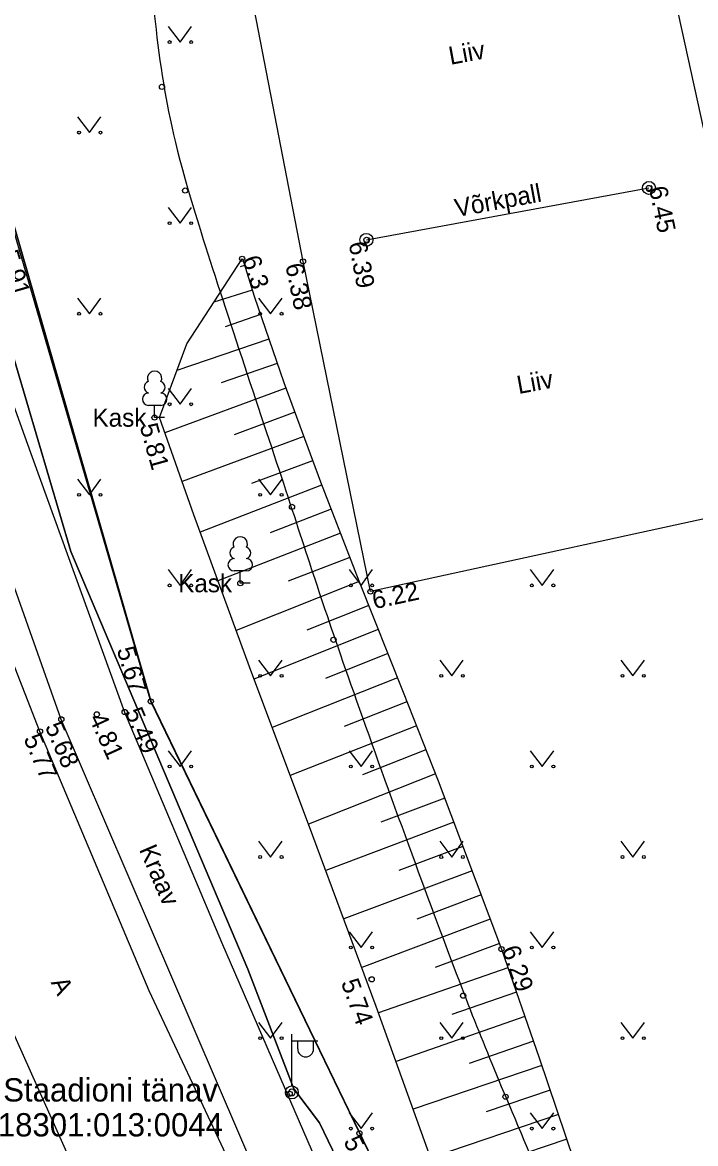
# Model space of a CAD drawing. Extents: x 473307 to 473719, y 6532843 to 6533381.
# Drawn here: x 473404.68 to 473430.7, y 6533111.89 to 6533155.23 of the extents above; entities that cross this region are included whole.
import ezdxf

# ---------------------------------------------------------------- set-up
doc = ezdxf.new("R2010")
doc.units = 0
for name, color, linetype in [('AED', 7, 'Continuous'), ('Default', 7, 'Continuous'), ('HALJASTUS', 7, 'Continuous'), ('KORGUS', 7, 'Continuous'), ('MPKAABEL', 7, 'Continuous'), ('PIIR', 7, 'Continuous'), ('POST', 7, 'Continuous'), ('PUU', 7, 'Continuous'), ('RAJATIS', 7, 'Continuous'), ('RELJEEF', 7, 'Continuous'), ('TEE', 7, 'Continuous'), ('VEEKOGU', 7, 'Continuous'), ('VTRASS', 7, 'Continuous')]:
    doc.layers.add(name, color=color, linetype=linetype)

# ---------------------------------------------------------------- blocks, each defined once
blk = doc.blocks.new('LEHTP1')
at = {"layer": 'Default'}
for p, q in [((0.48, 0.95), (-0.48, 0.95)), ((0, 0), (0, 0.95)), ((0.76, 0), (0, 0))]:
    blk.add_line(p, q, dxfattribs=at)
for centre, radius, start, end in [((0, 3.04), 0.554, 332.5799, 207.4201), ((-0.34, 2.345), 0.465, 109.02174, 253.14154), ((0.34, 2.345), 0.465, 286.85082, 70.98591), ((-0.475, 1.425), 0.475, 90.0016, 269.3953), ((0.475, 1.425), 0.475, 270.6047, 89.9984)]:
    blk.add_arc(centre, radius, start, end, dxfattribs=at)
blk = doc.blocks.new('MEPOST')
at = {"layer": 'Default'}
blk.add_circle((0, 0), 0.5, dxfattribs=at)
for start, end in [(0, 180), (180, 0)]:
    blk.add_arc((0, 0), 0.25, start, end, dxfattribs=at)
blk = doc.blocks.new('VAPOST')
at = {"layer": 'Default'}
for p, q in [((0, 0.5), (0, 4.5)), ((0, 4), (2, 4)), ((0.453, 3.358), (0.453, 4)), ((1.679, 3.358), (1.679, 4))]:
    blk.add_line(p, q, dxfattribs=at)
blk.add_arc((1.066, 3.358), 0.613, 180, 0, dxfattribs=at)
blk = doc.blocks.new('MURU')
at = {"layer": 'Default'}
for p, q in [((-0.927, 1.213), (0, 0)), ((0, 0), (0.891, 1.213))]:
    blk.add_line(p, q, dxfattribs=at)
for centre in [(-0.802, 0), (0.856, 0)]:
    blk.add_circle(centre, 0.11, dxfattribs=at)
blk = doc.blocks.new('PLPOST')
at = {"layer": 'Default'}
blk.add_circle((0, 0), 0.5, dxfattribs=at)
blk.add_arc((0, 0), 0.25, 225, 45, dxfattribs=at)

msp = doc.modelspace()

# ---------------------------------------------------------------- linework, layer by layer
at = {"layer": 'AED'}
msp.add_lwpolyline([(473572.372, 6533059.989), (473562.796, 6533044.25), (473549.715, 6533022.819), (473547.153, 6533018.61), (473538.777, 6533017.059), (473515.614, 6533013.019), (473502.84, 6533010.765), (473486.499, 6533007.9), (473486.322, 6533008.043), (473484.734, 6533009.635), (473455.331, 6533045.745), (473429.609, 6533087.699), (473409.64, 6533128.98), (473398.626, 6533166.806)], dxfattribs=at)
at = {"layer": 'KORGUS'}
for centre in [(473410.074, 6533152.735), (473410.969, 6533148.729), (473428.894, 6533148.828), (473417.974, 6533146.822), (473413.17, 6533146.089), (473415.525, 6533145.988), (473409.787, 6533139.955), (473415.098, 6533136.501), (473413.101, 6533133.548), (473418.132, 6533133.226), (473416.702, 6533131.364), (473409.64, 6533128.98), (473408.63, 6533128.571), (473406.183, 6533128.288), (473407.553, 6533128.48), (473405.358, 6533127.822), (473423.195, 6533119.408), (473418.179, 6533118.238), (473421.711, 6533117.606), (473415.008, 6533113.814), (473423.352, 6533113.701), (473417.704, 6533112.288)]:
    msp.add_circle(centre, 0.1, dxfattribs=at)
at = {"layer": 'MPKAABEL'}
for points in [[(473481.096, 6533010.082), (473475.299, 6533017.476), (473469.705, 6533025.438), (473464.809, 6533033.306), (473458.878, 6533040.236), (473452.764, 6533048.342), (473452.582, 6533049.145), (473450.829, 6533050.743), (473441.685, 6533065.704), (473432.314, 6533080.211), (473428.426, 6533086.609), (473420.464, 6533103.751), (473416.16, 6533112.695), (473415.168, 6533114.011), (473413.395, 6533118.629), (473406.551, 6533134.777), (473402.712, 6533147.764), (473401.357, 6533149.404), (473399.947, 6533154.634), (473395.886, 6533169.008), (473391.18, 6533184.279)], [(473401.357, 6533149.404), (473402.712, 6533147.764), (473406.551, 6533134.777), (473413.395, 6533118.629), (473415.168, 6533114.011)], [(473415.168, 6533114.011), (473416.16, 6533112.695), (473420.464, 6533103.751), (473428.426, 6533086.609), (473432.314, 6533080.211)]]:
    msp.add_lwpolyline(points, dxfattribs=at)
msp.add_open_spline([(473557.128, 6533166.896), (473557.202, 6533167.153), (473557.17, 6533167.374), (473557.049, 6533167.727), (473556.952, 6533168.034), (473556.879, 6533168.251), (473556.724, 6533168.7), (473555.529, 6533172.103), (473554.018, 6533176.143), (473551.965, 6533180.794), (473542.001, 6533194.467), (473528.815, 6533203.479), (473521.877, 6533205.787), (473521.549, 6533205.862), (473521.332, 6533205.91), (473521.125, 6533205.955), (473520.94, 6533205.994), (473520.783, 6533206.026), (473520.617, 6533205.983), (473520.549, 6533205.81), (473520.512, 6533205.71), (473520.33, 6533205.301), (473520.277, 6533205.676), (473520.247, 6533205.87), (473520.186, 6533205.982), (473520.155, 6533206.063), (473520.032, 6533206.188), (473519.647, 6533206.25), (473519.297, 6533206.303), (473518.91, 6533206.37), (473518.338, 6533206.457), (473517.785, 6533206.534), (473517.113, 6533206.617), (473504.722, 6533206.361), (473489.125, 6533201.073), (473481.589, 6533195.708), (473477.331, 6533191.94), (473475.034, 6533189.807), (473474.489, 6533189.292), (473474.068, 6533188.932), (473473.832, 6533188.684), (473473.679, 6533188.468), (473473.566, 6533188.217), (473473.476, 6533188.304), (473473.306, 6533188.406), (473473.134, 6533188.531), (473472.969, 6533188.652), (473471.778, 6533189.567), (473469.957, 6533190.966), (473467.155, 6533193.119), (473463.064, 6533196.262), (473458.646, 6533199.657), (473454.573, 6533202.786), (473453.666, 6533203.482), (473453.293, 6533203.769), (473452.995, 6533203.998), (473452.474, 6533204.222), (473452.213, 6533204.228), (473451.967, 6533204.234), (473451.474, 6533204.245), (473450.255, 6533204.273), (473449.394, 6533204.293), (473448.978, 6533204.302), (473448.578, 6533204.312), (473448.301, 6533204.318), (473447.638, 6533204.311), (473446.313, 6533204.297), (473445.312, 6533204.286), (473443.932, 6533204.272), (473441.622, 6533204.247), (473436.282, 6533204.191), (473430.619, 6533203.804), (473423.016, 6533203.284), (473416.174, 6533202.8), (473411.7, 6533202.424), (473406.989, 6533202.027), (473406.298, 6533201.969), (473405.901, 6533201.936), (473405.663, 6533201.916), (473405.247, 6533201.618), (473405.511, 6533201.478), (473405.706, 6533201.471), (473405.859, 6533201.485), (473406.073, 6533201.505), (473406.3, 6533201.526), (473406.699, 6533201.563), (473407.182, 6533201.607), (473407.617, 6533201.647), (473410.794, 6533201.939), (473414.597, 6533202.289), (473416.16, 6533202.433), (473416.748, 6533202.487), (473416.992, 6533202.509), (473417.116, 6533202.479), (473417.282, 6533202.408), (473417.308, 6533202.242), (473417.347, 6533201.989), (473417.396, 6533201.677), (473417.449, 6533201.337), (473417.509, 6533200.949), (473418.04, 6533197.53), (473418.813, 6533192.552), (473421.708, 6533179.543), (473422.341, 6533175.512), (473423.507, 6533169.632), (473424, 6533167.141), (473424.184, 6533166.215), (473424.244, 6533165.909), (473424.294, 6533165.662), (473424.314, 6533165.561), (473424.105, 6533164.865), (473423.816, 6533164.809), (473423.525, 6533164.753), (473422.668, 6533164.588), (473418.846, 6533164.247), (473414.425, 6533164.061), (473411.47, 6533164.651), (473411.357, 6533164.673), (473410.881, 6533164.787), (473410.433, 6533164.888), (473409.953, 6533164.731), (473409.752, 6533164.287), (473409.631, 6533163.669), (473409.502, 6533157.703), (473410.074, 6533152.735), (473410.969, 6533148.729), (473415.098, 6533136.501), (473416.702, 6533131.364), (473421.711, 6533117.606), (473423.352, 6533113.701), (473430.005, 6533097.933), (473437.623, 6533088.588), (473441.02, 6533084.73), (473450.501, 6533069.242), (473457.775, 6533058.053), (473462.215, 6533052.558), (473465.73, 6533047.735), (473467.401, 6533046.054), (473469.034, 6533044.411), (473472.353, 6533043.145), (473481.411, 6533040.582), (473489.023, 6533038.632), (473491.007, 6533038.103), (473491.686, 6533037.936), (473492.014, 6533037.852), (473492.476, 6533037.76), (473492.806, 6533038.095), (473492.829, 6533038.485), (473492.856, 6533039.18), (473492.795, 6533042.335), (473492.716, 6533044.024), (473492.683, 6533044.743), (473492.671, 6533044.987), (473492.823, 6533045.601), (473492.984, 6533045.289), (473492.985, 6533045.105), (473493.028, 6533044.585), (473493.105, 6533042.767), (473493.222, 6533039.506), (473493.206, 6533038.15), (473493.196, 6533038.01), (473493.2, 6533037.815), (473493.516, 6533037.437), (473493.94, 6533037.314), (473494.338, 6533037.204), (473496.451, 6533036.58), (473497.497, 6533036.067), (473498.11, 6533035.695), (473498.481, 6533035.454), (473498.784, 6533035.294), (473499.155, 6533035.524), (473499.568, 6533035.786), (473499.965, 6533035.642), (473500.381, 6533035.468), (473500.664, 6533035.366), (473501.255, 6533035.156), (473502.131, 6533034.826), (473503.015, 6533034.496), (473504.909, 6533033.785), (473507.281, 6533033.099), (473509.703, 6533032.392), (473510.465, 6533032.171), (473510.886, 6533032.05), (473511.297, 6533031.932), (473511.665, 6533031.668), (473511.711, 6533031.312), (473511.692, 6533030.835), (473511.632, 6533029.982), (473511.533, 6533028.937), (473511.486, 6533028.283), (473511.407, 6533027.141), (473511.358, 6533026.503), (473511.358, 6533025.257), (473511.617, 6533023.934), (473511.536, 6533023.5), (473511.414, 6533022.901), (473511.43, 6533022.205), (473511.677, 6533020.728), (473511.888, 6533019.916), (473512.37, 6533017.914), (473512.52, 6533015.831), (473512.626, 6533013.709), (473512.595, 6533013.242), (473512.387, 6533012.718), (473557.128, 6533166.896), (473512.387, 6533012.718)], degree=3, dxfattribs=at)
at = {"layer": 'PIIR'}
msp.add_lwpolyline([(473383.26, 6533220.83), (473372.23, 6533259.41), (473496.37, 6533266.79), (473499.84, 6533206.38), (473559.2, 6533209.37), (473561.43, 6533165.2), (473601.75, 6533167.04), (473607.56, 6533132.38), (473611.09, 6533109.85), (473618.6, 6533063.82), (473572.63, 6533056.43), (473548.5, 6533028.91), (473478.82, 6533017), (473455.33, 6533045.76), (473432.18, 6533083.36), (473429.59, 6533087.74), (473409.64, 6533129), (473385.1, 6533214.25), (473398.68, 6533216.8), (473398.11, 6533224.3)], close=True, dxfattribs=at)
msp.add_lwpolyline([(473385.1, 6533214.25), (473409.64, 6533129), (473429.59, 6533087.74), (473432.18, 6533083.36), (473455.33, 6533045.76), (473478.82, 6533017)], dxfattribs=at)
at = {"layer": 'RAJATIS'}
msp.add_lwpolyline([(473417.974, 6533146.822), (473428.894, 6533148.828)], dxfattribs=at)
at = {"layer": 'RELJEEF'}
for p, q in [((473413.263, 6533145.834), (473413.1, 6533145.783)), ((473413.561, 6533144.879), (473412.084, 6533144.419)), ((473413.879, 6533143.931), (473412.52, 6533143.465)), ((473414.203, 6533142.985), (473410.65, 6533141.766)), ((473414.527, 6533142.039), (473412.362, 6533141.296)), ((473414.857, 6533141.095), (473410.179, 6533139.366)), ((473415.203, 6533140.157), (473412.859, 6533139.29)), ((473415.55, 6533139.219), (473410.849, 6533137.482)), ((473415.897, 6533138.281), (473413.54, 6533137.41)), ((473416.245, 6533137.344), (473411.553, 6533135.52)), ((473416.608, 6533136.411), (473414.251, 6533135.496)), ((473416.97, 6533135.479), (473412.238, 6533133.641)), ((473417.332, 6533134.547), (473414.956, 6533133.624)), ((473417.694, 6533133.615), (473412.936, 6533131.724)), ((473418.064, 6533132.686), (473415.671, 6533131.735)), ((473418.433, 6533131.757), (473413.626, 6533129.846)), ((473418.802, 6533130.827), (473416.391, 6533129.869)), ((473419.172, 6533129.898), (473414.331, 6533127.974)), ((473419.541, 6533128.969), (473417.11, 6533128.008)), ((473419.908, 6533128.039), (473415.032, 6533126.111)), ((473420.276, 6533127.109), (473417.83, 6533126.142)), ((473420.644, 6533126.179), (473415.736, 6533124.239)), ((473421, 6533125.244), (473418.528, 6533124.315)), ((473421.352, 6533124.308), (473416.404, 6533122.448)), ((473421.704, 6533123.372), (473419.228, 6533122.441)), ((473422.056, 6533122.436), (473417.1, 6533120.573)), ((473422.408, 6533121.5), (473419.928, 6533120.568)), ((473422.76, 6533120.564), (473417.796, 6533118.698)), ((473423.112, 6533119.628), (473420.628, 6533118.694)), ((473423.445, 6533118.686), (473418.442, 6533116.95)), ((473423.773, 6533117.741), (473421.277, 6533116.875)), ((473424.101, 6533116.796), (473419.119, 6533115.068)), ((473424.428, 6533115.851), (473421.943, 6533114.989)), ((473424.754, 6533114.906), (473419.784, 6533113.221)), ((473425.075, 6533113.959), (473422.599, 6533113.119)), ((473425.396, 6533113.012), (473420.461, 6533111.339)), ((473425.717, 6533112.065), (473423.28, 6533111.239))]:
    msp.add_line(p, q, dxfattribs=at)
for points in [[(473460.393, 6533050.109), (473456.449, 6533054.165), (473452.955, 6533057.865), (473450.565, 6533061.44), (473445.545, 6533068.077), (473442.249, 6533072.557), (473438.329, 6533078.806), (473435.535, 6533083.2), (473432.144, 6533088.96), (473429.273, 6533093.898), (473424.744, 6533101.728), (473423.048, 6533105.375), (473420.571, 6533111.033), (473418.355, 6533117.193), (473415.908, 6533123.783), (473413.45, 6533130.316), (473411.307, 6533136.193), (473409.972, 6533139.949), (473411.039, 6533142.809), (473413.17, 6533146.089)], [(473413.181, 6533146.097), (473413.635, 6533144.642), (473414.778, 6533141.307), (473416.195, 6533137.474), (473417.681, 6533133.648), (473419.395, 6533129.336), (473420.75, 6533125.91), (473423.195, 6533119.408), (473424.654, 6533115.201), (473426.009, 6533111.203)]]:
    msp.add_lwpolyline(points, dxfattribs=at)
at = {"layer": 'TEE'}
for points in [[(473418.132, 6533133.226), (473415.525, 6533145.988), (473413.019, 6533158.968), (473428.553, 6533162.252), (473431.371, 6533149.393), (473433.987, 6533136.687), (473418.132, 6533133.226)], [(473486.74, 6533007.668), (473486.486, 6533007.568), (473485.836, 6533006.833), (473483.72, 6533004.961), (473480.798, 6533008.092), (473475.573, 6533014.142), (473470.165, 6533020.489), (473464.659, 6533026.983), (473458.607, 6533034.554), (473452.151, 6533042.899), (473444.547, 6533053.352), (473438.634, 6533062.682), (473435.33, 6533068.051), (473426.278, 6533084.212), (473422.195, 6533091.615), (473414.542, 6533107.225), (473409.577, 6533117.788), (473405.358, 6533127.822), (473401.846, 6533136.79), (473397.087, 6533149.814), (473394.968, 6533156.469), (473393.12, 6533161.978)]]:
    msp.add_lwpolyline(points, dxfattribs=at)
at = {"layer": 'VEEKOGU'}
for points in [[(473402.6, 6533145.241), (473405.051, 6533138.423), (473408.63, 6533128.571), (473412.37, 6533119.672), (473415.881, 6533111.58), (473424.05, 6533094.363), (473432.068, 6533080.056), (473438.112, 6533070.078), (473441.876, 6533064.003), (473447.577, 6533055.58), (473453.746, 6533046.091)], [(473452.326, 6533045.335), (473445.343, 6533054.161), (473439.616, 6533062.658), (473436.096, 6533068.575), (473429.941, 6533078.645), (473422.233, 6533093.292), (473413.911, 6533110.283), (473410.493, 6533118.237), (473406.183, 6533128.288), (473402.792, 6533137.828), (473400.309, 6533144.749)]]:
    msp.add_lwpolyline(points, dxfattribs=at)
at = {"layer": 'VTRASS'}
msp.add_lwpolyline([(473365.999, 6533272.186), (473364.518, 6533257.871), (473366.737, 6533240.392), (473372.861, 6533211.206), (473381.92, 6533180.915), (473385.845, 6533164.961), (473390.472, 6533150.34), (473401.875, 6533121.622), (473409.867, 6533103.775), (473420.281, 6533084.249), (473435.442, 6533057.262), (473447.562, 6533040.443), (473454.221, 6533030.196), (473471.046, 6533010.477), (473501.071, 6532979.442)], dxfattribs=at)

# ---------------------------------------------------------------- block references
at = {"layer": 'HALJASTUS', "xscale": 0.5, "yscale": 0.5}
for p in [(473410.771, 6533154.467), (473407.271, 6533150.967), (473410.771, 6533147.467), (473407.271, 6533143.967), (473414.271, 6533143.967), (473410.771, 6533140.467), (473407.271, 6533136.967), (473414.271, 6533136.967), (473410.771, 6533133.467), (473417.771, 6533133.467), (473424.771, 6533133.467), (473414.271, 6533129.967), (473421.271, 6533129.967), (473428.271, 6533129.967), (473410.771, 6533126.467), (473417.771, 6533126.467), (473424.771, 6533126.467), (473414.271, 6533122.967), (473421.271, 6533122.967), (473428.271, 6533122.967), (473417.771, 6533119.467), (473424.771, 6533119.467), (473414.271, 6533115.967), (473421.271, 6533115.967), (473428.271, 6533115.967), (473417.771, 6533112.467), (473424.771, 6533112.467)]:
    msp.add_blockref('MURU', p, dxfattribs=at)
at = {"layer": 'POST', "xscale": 0.5, "yscale": 0.5}
for name in ['VAPOST', 'MEPOST']:
    msp.add_blockref(name, (473415.093, 6533113.867), dxfattribs=at)
at = {"layer": 'PUU', "xscale": 0.5, "yscale": 0.5}
for p in [(473409.79, 6533139.95), (473413.1, 6533133.55)]:
    msp.add_blockref('LEHTP1', p, dxfattribs=at)
at = {"layer": 'RAJATIS', "xscale": 0.5, "yscale": 0.5}
for p in [(473428.894, 6533148.828), (473417.974, 6533146.822)]:
    msp.add_blockref('PLPOST', p, dxfattribs=at)

# ---------------------------------------------------------------- texts
at = {"layer": 'KORGUS'}
for s, rotation, p in [('6.45', 281.4773, (473428.894, 6533148.828)), ('5.91', 286.2329, (473403.822, 6533146.322)), ('6.39', 280.5929, (473417.286, 6533146.693)), ('6.3', 287.9174, (473413.17, 6533146.089)), ('6.38', 281.5454, (473414.839, 6533145.848)), ('5.81', 285.533, (473409.207, 6533139.628)), ('6.22', 12.314, (473418.281, 6533132.542)), ('5.67', 286.414, (473408.319, 6533130.988)), ('5.49', 292.7971, (473408.63, 6533128.571)), ('5.68', 293.2103, (473405.54, 6533128.012)), ('4.81', 294.5502, (473407.235, 6533128.335)), ('5.77', 292.8053, (473404.713, 6533127.551)), ('6.29', 289.2827, (473423.195, 6533119.408)), ('5.74', 289.9622, (473416.983, 6533118.117)), ('5.65', 296.1219, (473417.075, 6533111.98))]:
    msp.add_text(s, height=0.7, rotation=rotation, dxfattribs=at).set_placement(p)
at = {"layer": 'PIIR'}
for s, p in [('Staadioni tänav', (473403.939, 6533113.516)), ('18301:013:0044', (473403.729, 6533112.166))]:
    msp.add_text(s, height=0.9, dxfattribs=at).set_placement(p)
at = {"layer": 'PUU'}
for p in [(473407.39, 6533139.6), (473410.7, 6533133.2)]:
    msp.add_text('Kask', height=0.7, dxfattribs=at).set_placement(p)
at = {"layer": 'TEE'}
for s, rotation, p in [('Liiv', 10.4092, (473421.222, 6533153.585)), ('Võrkpall', 10.4092, (473421.458, 6533147.699)), ('Liiv', 10.4092, (473423.858, 6533140.862)), ('A', 296.8032, (473405.768, 6533118.118))]:
    msp.add_text(s, height=0.7, rotation=rotation, dxfattribs=at).set_placement(p)
at = {"layer": 'VEEKOGU'}
msp.add_text('Kraav', height=0.7, rotation=293.2091, dxfattribs=at).set_placement((473409.179, 6533123.259))

doc.saveas('drawing.dxf')
